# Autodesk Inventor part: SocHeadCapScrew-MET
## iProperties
Author: cdotson
Shininess: 64.0
PropertySet Name: _Private Model Information
Created: 2001-02
Part Number: SocHeadCapScrew-MET
Material: Default
Document SubType Name: Modeling
Designer: cdotson
Control State: 0
Master: False
Checked Out: False
PropertySet Name: Design Tracking Control
Density: 0.0
Volumn: 0.0
Area: 0.0
PropertySet Name: Model Information
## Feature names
1. Extrusion1
2. Extrusion2
3. Extrusion3
4. Chamfer1
